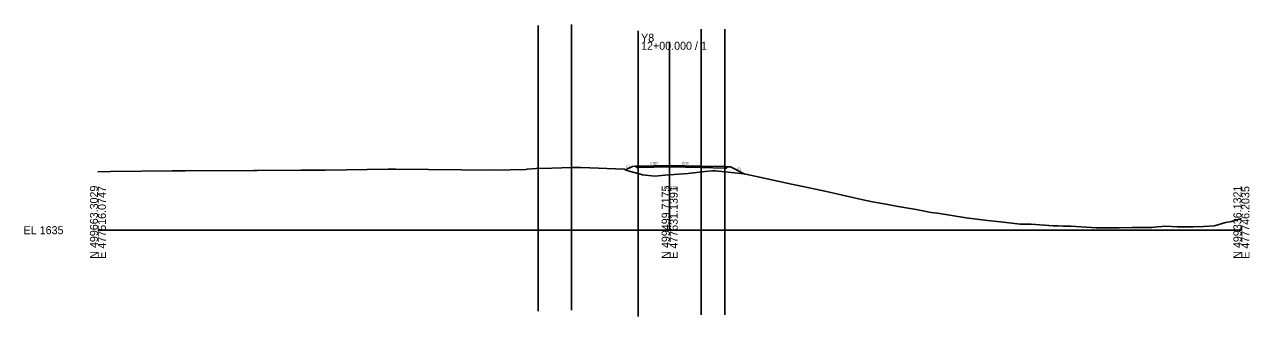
# Model space of a CAD drawing. Extents: x -26 to 403, y -10 to 2517.
# Drawn here: x -25.7 to 402.8, y 1969.8 to 2072 of the extents above; entities that cross this region are included whole.
import ezdxf

# ---------------------------------------------------------------- set-up
doc = ezdxf.new("R2010")
doc.units = 0
for name, color, linetype in [('Exist Cross Section Cell', 7, 'Continuous'), ('Exist XS Center Line Elevation Label', 7, 'Continuous'), ('Exist XS Ground Line', 7, 'Continuous'), ('Prop Road Sect_ Boring - Material (Outline)', 7, 'Continuous'), ('Prop XS Dump Level', 7, 'Continuous'), ('Prop XS Earthwork Shape', 7, 'Continuous'), ('Prop XS EOT Tick Mark', 7, 'Continuous'), ('Prop XS Finish Grade', 7, 'Continuous'), ('Prop XS Finish Grade Earthwork', 7, 'Continuous'), ('Prop XS Finish Grade Paved Shoulder', 7, 'Continuous'), ('Prop XS Finish Grade Pavement', 7, 'Continuous'), ('Prop XS Pvmt Edge Slope', 7, 'Continuous'), ('Prop XS SE Text', 7, 'Continuous'), ('Prop XS Side Slope Text', 7, 'Continuous'), ('Prop XS Subgrade Earthwork', 7, 'Continuous'), ('Scratch_Level_5', 7, 'Continuous')]:
    doc.layers.add(name, color=color, linetype=linetype)

msp = doc.modelspace()

# ---------------------------------------------------------------- linework, layer by layer
at = {"layer": 'Exist Cross Section Cell'}
for p, q in [((200, 2000), (200, 2065.94)), ((0, 2000), (200, 2000)), ((200, 2000), (400, 2000))]:
    msp.add_line(p, q, dxfattribs=at)
at = {"layer": 'Exist XS Ground Line'}
msp.add_lwpolyline([(0, 2020.47), (4.43, 2020.5), (25.98, 2020.8), (27.69, 2020.79), (30.61, 2020.8), (54.58, 2020.93), (55.85, 2020.93), (70.93, 2020.99), (79.62, 2021.04), (101.53, 2021.33), (103.52, 2021.36), (104.06, 2021.35), (138.72, 2020.95), (149.74, 2021.28), (150.19, 2021.32), (153.33, 2021.6), (158.76, 2021.75), (165.75, 2021.98), (169.03, 2021.97), (184.04, 2021.34), (185.06, 2020.93), (190.19, 2019.45), (190.52, 2019.42), (194.83, 2018.93), (198.32, 2019.24), (200, 2019.36), (206.49, 2019.82), (212.3, 2020.48), (214.95, 2020.78), (216, 2020.72), (225.92, 2019.7), (227.17, 2019.53), (230.38, 2018.73), (241.59, 2016.36), (242.6, 2016.14), (245.01, 2015.63), (254.83, 2013.58), (258.98, 2012.59), (267.06, 2010.78), (270.9, 2009.95), (276.36, 2008.95), (279.29, 2008.39), (286.23, 2007.2), (291.52, 2006.24), (293.75, 2005.91), (303.75, 2004.38), (311.13, 2003.41), (314.6, 2003), (315.77, 2002.91), (322.6, 2002.15), (326.43, 2002.07), (334.13, 2001.56), (335.89, 2001.5), (337.62, 2001.39), (340.37, 2001.35), (349.27, 2000.86), (351.06, 2000.87), (352.43, 2000.8), (357.21, 2000.82), (361.74, 2000.93), (368.67, 2000.96), (369.51, 2001.11), (373.48, 2001.35), (377.56, 2001.2), (379.88, 2001.16), (383.21, 2001.23), (386.7, 2001.27), (390.59, 2001.54), (394.42, 2002.69), (396.56, 2003.09), (400, 2004.12)], dxfattribs=at)
at = {"layer": 'Prop Road Sect_ Boring - Material (Outline)'}
for points in [[(188.43, 2021.91), (187.96, 2022.38), (188.99, 2022.46)], [(188.43, 2021.91), (187.96, 2022.38), (188.99, 2022.46)], [(219.32, 2022.3), (220.35, 2022.22), (219.88, 2021.75)], [(219.32, 2022.3), (220.35, 2022.22), (219.88, 2021.75)]]:
    msp.add_lwpolyline(points, close=True, dxfattribs=at)
at = {"layer": 'Prop XS Dump Level'}
for p, q in [((200, 2022.68), (188.99, 2022.46)), ((211.01, 2022.46), (200, 2022.68))]:
    msp.add_line(p, q, dxfattribs=at)
at = {"layer": 'Prop XS Earthwork Shape'}
msp.add_lwpolyline([(186.98, 2022.3), (184.6, 2021.11), (185.06, 2020.93), (190.19, 2019.45), (190.52, 2019.42), (194.83, 2018.93), (198.32, 2019.24), (200, 2019.36), (206.49, 2019.82), (212.3, 2020.48), (214.95, 2020.78), (216, 2020.72), (225.92, 2019.7), (226.32, 2019.64), (221.32, 2022.14), (220.35, 2022.22), (219.88, 2021.75), (219.32, 2021.76), (211.01, 2021.92), (200, 2022.14), (188.99, 2021.92), (188.43, 2021.91), (187.96, 2022.38)], close=True, dxfattribs=at)
at = {"layer": 'Prop XS EOT Tick Mark'}
for p, q in [((188.99, 2022.46), (188.99, 2023.46)), ((211.01, 2022.46), (211.01, 2023.46))]:
    msp.add_line(p, q, dxfattribs=at)
at = {"layer": 'Prop XS Finish Grade'}
for p, q in [((188.99, 2022.46), (187.96, 2022.38)), ((219.32, 2022.3), (220.35, 2022.22))]:
    msp.add_line(p, q, dxfattribs=at)
at = {"layer": 'Prop XS Finish Grade Earthwork'}
for p, q in [((186.98, 2022.3), (184.6, 2021.11)), ((187.96, 2022.38), (186.98, 2022.3)), ((220.35, 2022.22), (221.32, 2022.14)), ((221.32, 2022.14), (226.32, 2019.64))]:
    msp.add_line(p, q, dxfattribs=at)
at = {"layer": 'Prop XS Finish Grade Paved Shoulder'}
msp.add_line((211.01, 2022.46), (219.32, 2022.3), dxfattribs=at)
at = {"layer": 'Prop XS Finish Grade Pavement'}
for p, q in [((188.99, 2022.46), (200, 2022.68)), ((200, 2022.68), (211.01, 2022.46))]:
    msp.add_line(p, q, dxfattribs=at)
at = {"layer": 'Prop XS Pvmt Edge Slope'}
for p, q in [((188.99, 2022.46), (188.43, 2021.91)), ((219.32, 2022.3), (219.88, 2021.75))]:
    msp.add_line(p, q, dxfattribs=at)
at = {"layer": 'Prop XS Subgrade Earthwork'}
for p, q in [((188.43, 2021.91), (187.96, 2022.38)), ((188.99, 2021.92), (188.43, 2021.91)), ((200, 2022.14), (188.99, 2021.92)), ((211.01, 2021.92), (200, 2022.14)), ((211.01, 2021.92), (219.32, 2021.76)), ((219.32, 2021.76), (219.88, 2021.75)), ((219.88, 2021.75), (220.35, 2022.22))]:
    msp.add_line(p, q, dxfattribs=at)
at = {"layer": 'Scratch_Level_5'}
for p, q in [((153.99, 2071.62), (153.99, 1971.62)), ((165.67, 2071.98), (165.67, 1971.98)), ((211.01, 2070.33), (211.01, 1970.33)), ((219.32, 2070.37), (219.32, 1970.37)), ((188.99, 2069.8), (188.99, 1969.8))]:
    msp.add_line(p, q, dxfattribs=at)

# ---------------------------------------------------------------- texts
at = {"layer": 'Exist Cross Section Cell'}
for s, p in [('Y8', (190, 2065.94)), ('12+00.000 / 1', (190, 2063.14)), ('EL 1635', (-26, 1998.6))]:
    msp.add_text(s, height=2.8, dxfattribs=at).set_placement(p)
for s, p in [('N 499663.3029', (0, 1990)), ('E 477516.0747', (2.8, 1990)), ('N 499499.7175', (200, 1990)), ('E 477631.1391', (202.8, 1990)), ('N 499336.1321', (400, 1990)), ('E 477746.2035', (402.8, 1990))]:
    msp.add_text(s, height=2.8, rotation=90, dxfattribs=at).set_placement(p)
at = {"layer": 'Exist XS Center Line Elevation Label'}
msp.add_text('1654.36', height=0.9, dxfattribs=at).set_placement((197.94, 2014.46))
at = {"layer": 'Prop XS Dump Level'}
msp.add_text('Case1', height=0.04, dxfattribs=at).set_placement((186.98, 2022.26))
at = {"layer": 'Prop XS SE Text'}
for rotation, p in [(1.1458, (193.24, 2023.05)), (358.8542, (204.25, 2023.1))]:
    msp.add_text('0.020', height=0.75, rotation=rotation, dxfattribs=at).set_placement(p)
at = {"layer": 'Prop XS Side Slope Text'}
for rotation, p in [(26.5651, (184.9, 2021.7)), (333.5604, (223.6, 2021.4))]:
    msp.add_text('2:1', height=0.75, rotation=rotation, dxfattribs=at).set_placement(p)

doc.saveas('drawing.dxf')
